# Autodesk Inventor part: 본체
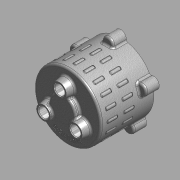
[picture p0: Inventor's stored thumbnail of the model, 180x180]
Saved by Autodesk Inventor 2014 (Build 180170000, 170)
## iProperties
Created: 2015-11
Part Number: 본체
Document SubType Name: 모델링
Designer: mdu
Material: 알루미늄 6061
Density: 1 g/cm^3
Appearance: 알루미늄 - 평지
변환 표준: STEP AP214IS
파일 이름: C:\Users\SeoGD\Desktop\?쒗뿕\紐몄껜.stp
전처리기: Build: 253, Release: 2010 SP1 - Date: Wed 07/29/2009
전송 단위: 밀리미터
불확실성: 0.01
Author: mdu
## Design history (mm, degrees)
sketch "스케치2"
  geometry: C1 r 50 at (0, 0); 1 further point
  constraints: 1 centre point, 1 coincident
  dimensions: "d9" = 100 diameter of C1
extrude "돌출2" new body sketch "스케치2" distance "d10" = 80; taper "d11" = 0 deg
feature "쉘1" dims "d12" = 5
sketch "스케치3" dims "d13" = 55
  geometry: C1 r 7.5 at (0, 27.5); C2 r 12.5 at (0, 27.5); 2 further points
  constraints: 2 centre point, 2 coincident, 2 vertical alignment, 2 other
  dimensions: "d14" = 15 diameter of C1; "d15" = 25 diameter of C2
extrude "돌출3" join sketch "스케치3" distance "d16" = 12; taper "d17" = -10 deg
hole "구멍2" diameter "d20" = 15; stored, may be unused: countersink angle "d24" = 90 deg, drill point angle "d26" = 118 deg; dims "d18" = 10, "d19" = 10, "d21" = 6, "d22" = 4, "d23" = 2, "d25" = 15
chamfer "모따기1" distance "d27" = 1; stored, may be unused: second distance "d28" = 2, angle "d29" = 45 deg
sketch "스케치4"
  geometry: L1 (0, 0)-(0, 88); L2 (0, 70)-(13.16, 70); L3 (-45, 75)-(45, 75) reference; L4 (-50, 80)-(50, 80) reference; L5 (13.16, 70)-(14.5, 75); L6 (20, 80)-(20, 88); L7 (20, 88)-(0, 88); L8 (20, 80)-(14.5, 75)
  constraints: 12 end point, 3 point on line, 2 perpendicular, 1 vertical
  dimensions: "d34" = 40 diameter of L6 L1; "d35" = 105 deg angle of L5 L3; "d36" = 5 distance between parallel lines of L2 L3; "d37" = 8 distance between parallel lines of L7 L4; "d51" = 29 diameter of L5.end L1
revolve "회전1" sketch "스케치4" stored, may be unused: angle "d38" = 90 deg
hole "구멍3" diameter "d41" = 15; stored, may be unused: countersink angle "d45" = 90 deg, drill point angle "d47" = 0 deg; dims "d39" = 10, "d40" = 10, "d42" = 6, "d43" = 22, "d44" = 13, "d46" = 15
chamfer "모따기2" distance "d48" = 1; stored, may be unused: second distance "d49" = 2, angle "d50" = 45 deg
fillet "모깎기1" dims "d52" = 3
fillet "모깎기2" dims "d53" = 3, "d72" = 0.2
sketch "스케치5"
  geometry: A1 r 50 centre (0, 0) between (50, 0) and (-8.074, 49.344) reference; A2 r 8.5 centre (0, 52) between (8.074, 49.344) and (-8.074, 49.344); 1 further point
  constraints: 5 point on circle, 1 centre point, 1 horizontal alignment
  dimensions: "d54" = 90 deg dimension on point (0, 0) A2.centre A1.start; "d55" = 52 distance of A2.centre point (0, 0); "d56" = 17 diameter of A2
extrude "돌출4" join sketch "스케치5" distance "d57" = 20; taper "d58" = 0 deg
fillet "모깎기3" dims "d59" = 3
hole "구멍4" diameter "d62" = 4.134; stored, may be unused: countersink angle "d66" = 90 deg, drill point angle "d68" = 118 deg; dims "d60" = 10, "d61" = 10, "d63" = 12, "d64" = 22, "d65" = 13, "d67" = 15
sketch "스케치6"
  geometry: C1 r 47 at (0, 0) reference; C2 r 42.5 at (0, 0); 1 further point
  constraints: 1 centre point, 1 coincident, 1 other
  dimensions: "d73" = 85 diameter of C2
feature "엠보싱1" sketch "스케치6" dims "d74" = 0.5, "d75" = 0
node "작업 평면1"
sketch "스케치7"
  geometry: A1 r 50 centre (0, 0) between (5.144, 49.735) and (-5.144, 49.735) reference; A2 r 3 centre (0, 47.916) between (2.204, 49.951) and (-2.204, 49.951); 1 further point
  constraints: 4 point on circle, 1 centre point, 1 vertical alignment
  dimensions: "d77" = 3 radius of A2
extrude "돌출5" join sketch "스케치7" distance "d79" = 15; taper "d80" = 0 deg
fillet "모깎기4" dims "d81" = 1
fillet "모깎기5" dims "d82" = 1
node "솔리드1"
node "솔리드 본체"
node "곡면 본체"
pattern_circular "원형 패턴1" dims "d31" = 360 deg
pattern_circular "원형 패턴2" dims "d70" = 360 deg
pattern_circular "원형 패턴3" dims "d84" = 360 deg
pattern_linear "직사각형 패턴1" dims "d89" = 25
node "솔리드2"
